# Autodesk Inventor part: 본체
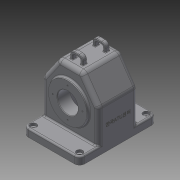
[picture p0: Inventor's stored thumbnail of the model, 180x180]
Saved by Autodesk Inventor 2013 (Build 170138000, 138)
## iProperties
Created: 2016-12
Part Number: 본체
Material: 일반
Document SubType Name: Modeling
Designer: Administrator
Density: 1 g/cm^3
Author: Administrator
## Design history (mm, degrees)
node "Front"
node "Right"
node "Top"
sketch "스케치1"
  geometry: L1 (-55, 75)-(55, 75); L2 (55, 75)-(55, -75); L3 (55, -75)-(-55, -75); L4 (-55, -75)-(-55, 75); 3 further points
  constraints: 8 end point, 2 midpoint, 2 parallel, 1 horizontal, 1 horizontal alignment, 1 perpendicular, 1 vertical alignment
  dimensions: "d3" = 110 distance of L1.start L1.end; "d5" = 150 distance of L3.end L1.start
extrude "돌출1" new body sketch "스케치1" distance "d6" = 15; taper "d7" = 0 deg
fillet "모깎기1" dims "d8" = 10
sketch "스케치2"
  geometry: L1 (45, 15)-(-45, 15) reference; L2 (-55, 0)-(-55, 15) reference; L3 (55, 15)-(55, 0) reference; L4 (-55, 15)-(-55, 80); L5 (-55, 80)-(-23.491, 125); L6 (-23.491, 125)-(23.491, 125); L7 (23.491, 125)-(55, 80); L8 (55, 80)-(55, 15); L9 (-55, 15)-(55, 15); 2 further points
  constraints: 12 end point, 2 parallel, 1 equal length, 1 horizontal, 1 midpoint, 1 perpendicular, 1 vertical alignment
  dimensions: "d9" = 65 distance of L7.end L3.start; "d10" = 110 vertical distance of L6.end L3.start; "d13" = 35 deg angle of L5 L4
extrude "돌출2" join sketch "스케치2" stored distance "d11" = 77; taper "d12" = 0 deg
sketch "스케치3"
  geometry: C1 r 37.5 at (0, 65); 1 further point
  constraints: 1 centre point, 1 vertical alignment
  dimensions: "d14" = 75 diameter of C1; "d16" = 65 distance of C1.centre point (0, 0)
extrude "돌출3" join sketch "스케치3" distance "d17" = 5; taper "d18" = 0 deg
sketch "스케치4"
  geometry: L1 (-55, 80)-(-55, 15) reference; L2 (55, 15)-(-55, 15) reference; L3 (55, 15)-(55, 80) reference; L4 (55, 80)-(23.491, 125) reference; L5 (23.491, 125)-(-23.491, 125) reference; L6 (-23.491, 125)-(-55, 80) reference; L7 (-20.888, 120)-(20.888, 120); L8 (20.888, 120)-(50, 78.424); L9 (50, 78.424)-(50, 20); L10 (50, 20)-(-50, 20); L11 (-50, 20)-(-50, 78.424); L12 (-50, 78.424)-(-20.888, 120); L13 (-45, 0)-(45, 0) reference; L14 (-50, 0)-(-50, 78.424); L15 (-20.888, 120)-(20.888, 120); L16 (50, 78.424)-(50, 0); L17 (50, 0)-(-50, 0); L18 (-50, 78.424)-(-20.888, 120); L19 (20.888, 120)-(50, 78.424); C1 r 37.5 at (0, 65) reference; 3 further points
  constraints: 24 end point, 5 collinear, 3 midpoint, 1 perpendicular, 5 other
  dimensions: "d19" = 5 distance between parallel lines of L6 L12
extrude "돌출4" cut sketch "스케치4" stored distance "d20" = 67; taper "d21" = 0 deg
sketch "스케치5"
  geometry: L1 (-59.812, 65)-(63.146, 65); L2 (-19.5, 65)-(-19.5, 92); L3 (-19.5, 92)-(-33.5, 106); L4 (-33.5, 106)-(-33.5, 65); L5 (-19.5, 65)-(-33.5, 65); L6 (-33.5, 120)-(-33.5, 78.424) reference; L7 (-43.5, 102.5)-(-43.5, 27.5) reference; 1 further point
  constraints: 10 end point, 2 collinear, 2 perpendicular, 2 point on line, 1 horizontal
  dimensions: "d22" = 65 distance from line of L1 point (0, 0); "d23" = 45 deg angle of L3 L2; "d24" = 54 diameter of L2.end L1; "d25" = 24 distance between parallel lines of L2 L7
revolve "회전1" sketch "스케치5" stored, may be unused: angle "d26" = 90 deg
sketch "스케치6"
  geometry: C1 r 37.5 at (0, -65) reference; C2 r 31 at (0, -65); 1 further point
  constraints: 1 centre point, 1 coincident
  dimensions: "d27" = 62 diameter of C2
extrude "돌출5" join sketch "스케치6" distance "d29" = 10; taper "d30" = 0 deg
sketch "스케치7"
  geometry: C1 r 37.5 at (0, 0) reference; C2 r 20 at (0, 0); 1 further point
  constraints: 1 centre point, 1 coincident
  dimensions: "d31" = 40 diameter of C2
extrude "돌출6" cut sketch "스케치7" stored distance "d33" = 10; taper "d34" = 0 deg
chamfer "모따기1" distance "d35" = 1; stored, may be unused: second distance "d36" = 2, angle "d37" = 45 deg
fillet "모깎기2" dims "d38" = 3
fillet "모깎기3" dims "d39" = 10
fillet "모깎기4" dims "d40" = 8
fillet "모깎기5" dims "d41" = 3
sketch "스케치8"
  geometry: C1 r 37.5 at (0, 0) reference; 2 further points
  constraints: 1 vertical alignment
  dimensions: "d42" = 29 distance of point (0, 29) C1.centre
hole "구멍1" sketch "스케치8" at (0, 29) diameter "d43" = 2.459; stored, may be unused: countersink angle "d47" = 90 deg, drill point angle "d49" = 118 deg; dims "d44" = 6, "d45" = 4, "d46" = 2, "d48" = 8
node "작업 평면4"
sketch "스케치9"
  geometry: L1 (-18.285, 125)-(18.285, 125) reference; L2 (-12.5, 125)-(-12.5, 132); L3 (-4.5, 140)-(4.5, 140); L4 (12.5, 132)-(12.5, 125); L5 (-12.5, 125)-(-7.5, 125); L6 (-12.5, 125)-(12.5, 125); A1 r 8 centre (-4.5, 132) between (-4.5, 140) and (-12.5, 132); A2 r 8 centre (4.5, 132) between (12.5, 132) and (4.5, 140); 4 further points
  constraints: 10 end point, 7 point on line, 4 point on circle, 4 tangent, 3 perpendicular, 2 centre point, 1 collinear, 1 equal radius, 1 midpoint, 1 vertical alignment
  dimensions: "d54" = 25 distance of point (-12.5, 140) point (12.5, 140); "d57" = 140 distance of point (0, 0) point (0, 140); "d62" = 8 radius of A1
extrude "돌출8" join sketch "스케치9" distance "d63" = 8; taper "d64" = 0 deg
sketch "스케치10"
  geometry: L1 (4.5, 140)-(-4.5, 140) reference; L2 (12.5, 125)-(-12.5, 125) reference; L3 (-4.5, 135)-(4.5, 135); L4 (7.5, 132)-(7.5, 125); L5 (7.5, 130)-(-7.5, 130); L6 (-7.5, 125)-(-7.5, 132); L7 (-7.5, 125)-(7.5, 125); A1 r 8 centre (4.5, 132) between (12.5, 132) and (4.5, 140) reference; A2 r 8 centre (-4.5, 132) between (-4.5, 140) and (-12.5, 132) reference; A3 r 3 centre (4.5, 132) between (7.5, 132) and (4.5, 135); A4 r 3 centre (-4.5, 132) between (-4.5, 135) and (-7.5, 132); 1 further point
  constraints: 10 end point, 4 point on circle, 4 point on line, 2 centre point, 2 tangent, 1 equal radius, 1 perpendicular, 1 vertical, 1 other
  dimensions: "d65" = 5 distance between parallel lines of L1 L3
extrude "돌출9" cut sketch "스케치10" distance "d66" = 8; taper "d67" = 0 deg
fillet "모깎기7" dims "d68" = 1
sketch "스케치11"
  geometry: A1 r 7 centre (-45, -65) between (-52, -65) and (-45, -72) reference; A2 r 7 centre (45, -65) between (45, -72) and (52, -65) reference; 3 further points
  constraints: 2 coincident
hole "구멍2" sketch "스케치11" at (-45, -65), (45, -65) diameter "d69" = 5; stored, may be unused: countersink angle "d73" = 90 deg, drill point angle "d75" = 118 deg; dims "d70" = 6, "d71" = 12, "d72" = 5, "d74" = 15
sketch "스케치12"
  geometry: C1 r 20 at (0, 0) reference; 2 further points
  constraints: 1 vertical alignment
  dimensions: "d76" = 26 distance of point (0, -26) C1.centre
hole "구멍3" sketch "스케치12" at (0, -26) diameter "d77" = 2.459; stored, may be unused: countersink angle "d81" = 90 deg, drill point angle "d83" = 118 deg; dims "d78" = 6, "d79" = 12, "d80" = 5, "d82" = 8
chamfer "모따기2" distance "d87" = 1; stored, may be unused: second distance "d88" = 2, angle "d89" = 45 deg
sketch "스케치13"
  geometry: L1 (0, 130)-(0, 0) reference; L2 (-51.833, 38.769)-(-38.167, 91.231); L3 (-76.847, 26.5)-(-18, 26.5) reference; 4 further points
  constraints: 2 end point, 1 midpoint, 1 other
  dimensions: "d90" = 45 distance from line of point (-45, 65) L1; "d91" = 38.5 distance from line of point (-45, 65) L3
extrude "돌출10" join sketch "스케치13" distance "d92" = 0.5; taper "d93" = 0 deg; dims "d9" = 65, "d50" = 40
fillet "모깎기8" dims "d94" = 5
node "본체"
pattern_circular "원형 패턴1" dims angle "d51" = 360 deg
mirror "대칭2"
mirror "대칭3"
pattern_circular "원형 패턴2" dims angle "d85" = 360 deg
node "투영된 루프1"
other parameters: "d0" = 0, "d1" = 0, "d2" = 0, "d53" = 26
